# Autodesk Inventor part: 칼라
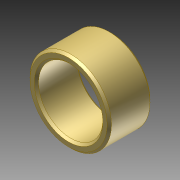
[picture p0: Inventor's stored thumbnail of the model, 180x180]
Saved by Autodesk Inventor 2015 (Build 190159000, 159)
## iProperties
Created: 2026-07
Part Number: 칼라
Material: 일반
Document SubType Name: Modeling
Designer: USER
Density: 1 g/cm^3
Appearance: 기본값
Author: USER
Author: jhkim
Creation Date: 2026-07-01
Sending System: Autodesk Inventor 2027
Preprocessor: ST-DEVELOPER v20.1
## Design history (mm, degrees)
node "칼라1"
node "솔리드1"
node "기준1"
